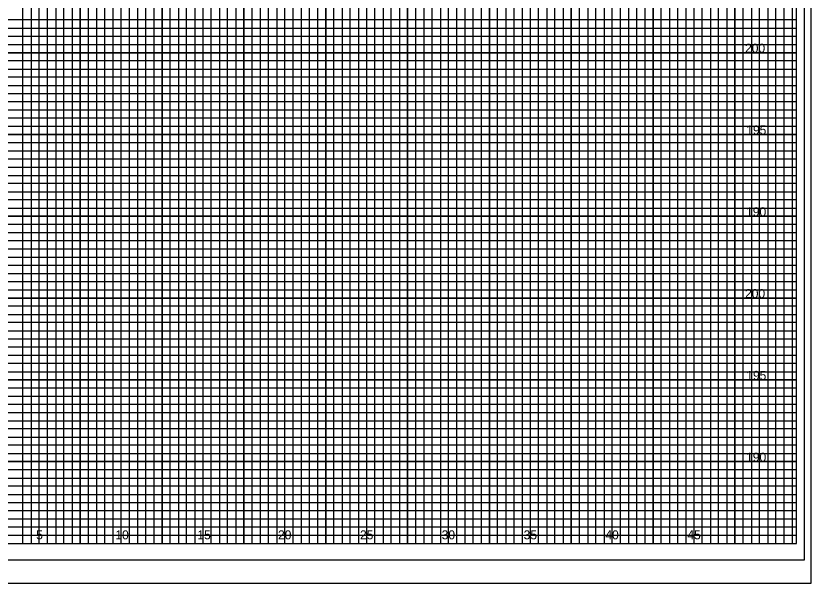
# Model space of a CAD drawing. Extents: x -4 to 103, y -2 to 209.
# Drawn here: x 54.82 to 103.4, y -2.43 to 32.25 of the extents above; entities that cross this region are included whole.
import ezdxf

# ---------------------------------------------------------------- set-up
doc = ezdxf.new("R2010")
doc.units = 0
for name, color, linetype in [('Exist XS Ground Line', 7, 'Continuous'), ('Old_Level_10', 7, 'Continuous'), ('Old_Level_3', 7, 'Continuous'), ('Old_Level_5', 7, 'Continuous'), ('Old_Level_8', 7, 'Continuous'), ('Prop XS Dump Level', 7, 'Continuous'), ('Prop XS Elevation Labels', 7, 'Continuous'), ('Prop XS Finish Grade', 7, 'Continuous'), ('Prop XS Label Text', 7, 'Continuous')]:
    doc.layers.add(name, color=color, linetype=linetype)

msp = doc.modelspace()

# ---------------------------------------------------------------- linework, layer by layer
at = {"layer": 'Exist XS Ground Line'}
msp.add_lwpolyline([(103, 66), (-2.8, 66), (-2.8, -1), (103, -1)], close=True, dxfattribs=at)
at = {"layer": 'Old_Level_10'}
for p, q in [((56.25, 0), (56.25, 65)), ((58.75, 0), (58.75, 65)), ((61.25, 0), (61.25, 65)), ((63.75, 0), (63.75, 65)), ((66.25, 0), (66.25, 65)), ((68.75, 0), (68.75, 65)), ((71.25, 0), (71.25, 65)), ((73.75, 0), (73.75, 65)), ((91.25, 0), (91.25, 63.425)), ((93.75, 0), (93.75, 63.425)), ((96.25, 0), (96.25, 63.425)), ((98.75, 0), (98.75, 63.425)), ((101.25, 0), (101.25, 63.425)), ((76.25, 0), (76.25, 62)), ((78.75, 0), (78.75, 62)), ((81.25, 0), (81.25, 62)), ((83.75, 0), (83.75, 62)), ((86.25, 0), (86.25, 62)), ((88.75, 0), (88.75, 62)), ((0, 30), (102.5, 30)), ((0, 27.5), (102.5, 27.5)), ((0, 25), (102.5, 25)), ((0, 22.5), (102.5, 22.5)), ((0, 20), (102.5, 20)), ((0, 17.5), (102.5, 17.5)), ((0, 15), (102.5, 15)), ((0, 12.5), (102.5, 12.5)), ((0, 10), (102.5, 10)), ((0, 7.5), (102.5, 7.5)), ((0, 5), (102.5, 5)), ((0, 2.5), (102.5, 2.5))]:
    msp.add_line(p, q, dxfattribs=at)
at = {"layer": 'Old_Level_3'}
msp.add_line((-3.5, -2.425), (103.4, -2.425), dxfattribs=at)
at = {"layer": 'Old_Level_5'}
msp.add_lwpolyline([(103.4, 67.4), (-3.5, 67.4), (-3.5, -2.425), (103.4, -2.425)], close=True, dxfattribs=at)
at = {"layer": 'Old_Level_8'}
for points in [[(56.25, 0), (56.25, 65)], [(58.75, 65), (58.75, 0), (61.25, 0), (61.25, 65)], [(63.75, 65), (63.75, 0), (66.25, 0), (66.25, 65)], [(68.75, 65), (68.75, 0), (71.25, 0), (71.25, 65)], [(73.75, 65), (73.75, 0), (76.25, 0), (76.25, 62)], [(88.75, 62), (88.75, 0), (91.25, 0), (91.25, 63.425)], [(93.75, 63.425), (93.75, 0), (96.25, 0), (96.25, 63.425)], [(98.75, 63.425), (98.75, 0), (101.25, 0), (101.25, 63.425)], [(78.75, 62), (78.75, 0), (81.25, 0), (81.25, 62)], [(83.75, 62), (83.75, 0), (86.25, 0), (86.25, 62)], [(0, 27.5), (102.5, 27.5), (102.5, 30), (0, 30)], [(0, 22.5), (102.5, 22.5), (102.5, 25), (0, 25)], [(0, 17.5), (102.5, 17.5), (102.5, 20), (0, 20)], [(0, 12.5), (102.5, 12.5), (102.5, 15), (0, 15)], [(0, 7.5), (102.5, 7.5), (102.5, 10), (0, 10)], [(0, 2.5), (102.5, 2.5), (102.5, 5), (0, 5)]]:
    msp.add_lwpolyline(points, dxfattribs=at)
at = {"layer": 'Prop XS Dump Level'}
msp.add_lwpolyline([(102.5, 65), (0, 65), (0, 0), (102.5, 0)], close=True, dxfattribs=at)
at = {"layer": 'Prop XS Finish Grade'}
for points in [[(54.75, 0), (55.25, 0), (55.25, 65)], [(55.75, 65), (55.75, 0), (56.75, 0), (56.75, 65)], [(57.25, 65), (57.25, 0), (57.75, 0), (57.75, 65)], [(58.25, 65), (58.25, 0), (59.25, 0), (59.25, 65)], [(59.75, 65), (59.75, 0), (60.25, 0), (60.25, 65)], [(60.75, 65), (60.75, 0), (61.75, 0), (61.75, 65)], [(62.25, 65), (62.25, 0), (62.75, 0), (62.75, 65)], [(63.25, 65), (63.25, 0), (64.25, 0), (64.25, 65)], [(64.75, 65), (64.75, 0), (65.25, 0), (65.25, 65)], [(65.75, 65), (65.75, 0), (66.75, 0), (66.75, 65)], [(67.25, 65), (67.25, 0), (67.75, 0), (67.75, 65)], [(68.25, 65), (68.25, 0), (69.25, 0), (69.25, 65)], [(69.75, 65), (69.75, 0), (70.25, 0), (70.25, 65)], [(70.75, 65), (70.75, 0), (71.75, 0), (71.75, 65)], [(72.25, 65), (72.25, 0), (72.75, 0), (72.75, 65)], [(73.25, 65), (73.25, 0), (74.25, 0), (74.25, 62)], [(89.75, 62), (89.75, 0), (90.25, 0), (90.25, 63.425)], [(90.75, 63.425), (90.75, 0), (91.75, 0), (91.75, 63.425)], [(92.25, 63.425), (92.25, 0), (92.75, 0), (92.75, 63.425)], [(93.25, 63.425), (93.25, 0), (94.25, 0), (94.25, 63.425)], [(94.75, 63.425), (94.75, 0), (95.25, 0), (95.25, 63.425)], [(95.75, 63.425), (95.75, 0), (96.75, 0), (96.75, 63.425)], [(97.25, 63.425), (97.25, 0), (97.75, 0), (97.75, 63.425)], [(98.25, 63.425), (98.25, 0), (99.25, 0), (99.25, 63.425)], [(99.75, 63.425), (99.75, 0), (100.25, 0), (100.25, 63.425)], [(100.25, 63.425), (100.75, 63.425), (100.75, 0), (101.75, 0), (101.75, 63.425), (102.25, 63.425), (102.25, 0)], [(74.75, 62), (74.75, 0), (75.25, 0), (75.25, 62)], [(75.75, 62), (75.75, 0), (76.75, 0), (76.75, 62)], [(77.25, 62), (77.25, 0), (77.75, 0), (77.75, 62)], [(78.25, 62), (78.25, 0), (79.25, 0), (79.25, 62)], [(79.75, 62), (79.75, 0), (80.25, 0), (80.25, 62)], [(80.75, 62), (80.75, 0), (81.75, 0), (81.75, 62)], [(82.25, 62), (82.25, 0), (82.75, 0), (82.75, 62)], [(83.25, 62), (83.25, 0), (84.25, 0), (84.25, 62)], [(84.75, 62), (84.75, 0), (85.25, 0), (85.25, 62)], [(85.75, 62), (85.75, 0), (86.75, 0), (86.75, 62)], [(87.25, 62), (87.25, 0), (87.75, 0), (87.75, 62)], [(88.25, 62), (88.25, 0), (89.25, 0), (89.25, 62)], [(0, 31.5), (102.5, 31.5), (102.5, 32), (0, 32)], [(0, 30.5), (102.5, 30.5), (102.5, 31), (0, 31)], [(0, 29), (102.5, 29), (102.5, 29.5), (0, 29.5)], [(0, 28), (102.5, 28), (102.5, 28.5), (0, 28.5)], [(0, 26.5), (102.5, 26.5), (102.5, 27), (0, 27)], [(0, 25.5), (102.5, 25.5), (102.5, 26), (0, 26)], [(0, 24), (102.5, 24), (102.5, 24.5), (0, 24.5)], [(0, 23), (102.5, 23), (102.5, 23.5), (0, 23.5)], [(0, 21.5), (102.5, 21.5), (102.5, 22), (0, 22)], [(0, 20.5), (102.5, 20.5), (102.5, 21), (0, 21)], [(0, 19), (102.5, 19), (102.5, 19.5), (0, 19.5)], [(0, 18), (102.5, 18), (102.5, 18.5), (0, 18.5)], [(0, 16.5), (102.5, 16.5), (102.5, 17), (0, 17)], [(0, 15.5), (102.5, 15.5), (102.5, 16), (0, 16)], [(0, 14), (102.5, 14), (102.5, 14.5), (0, 14.5)], [(0, 13), (102.5, 13), (102.5, 13.5), (0, 13.5)], [(0, 11.5), (102.5, 11.5), (102.5, 12), (0, 12)], [(0, 10.5), (102.5, 10.5), (102.5, 11), (0, 11)], [(0, 9), (102.5, 9), (102.5, 9.5), (0, 9.5)], [(0, 8), (102.5, 8), (102.5, 8.5), (0, 8.5)], [(0, 6.5), (102.5, 6.5), (102.5, 7), (0, 7)], [(0, 5.5), (102.5, 5.5), (102.5, 6), (0, 6)], [(0, 4), (102.5, 4), (102.5, 4.5), (0, 4.5)], [(0, 3), (102.5, 3), (102.5, 3.5), (0, 3.5)], [(0, 1.5), (102.5, 1.5), (102.5, 2), (0, 2)], [(0, 0.5), (102.5, 0.5), (102.5, 1), (0, 1)]]:
    msp.add_lwpolyline(points, dxfattribs=at)

# ---------------------------------------------------------------- texts
at = {"layer": 'Prop XS Elevation Labels'}
for s, p in [('5', (56.0574, 0.25)), ('10', (60.8971, 0.25)), ('15', (65.9057, 0.25)), ('20', (70.8312, 0.25)), ('25', (75.8399, 0.25)), ('30', (80.8312, 0.25)), ('35', (85.8399, 0.25)), ('40', (90.8313, 0.25)), ('45', (95.8399, 0.25))]:
    msp.add_text(s, height=0.55, dxfattribs=at).set_placement(p)
at = {"layer": 'Prop XS Label Text'}
for s, p in [('200', (99.3638, 30)), ('195', (99.4383, 25)), ('190', (99.4296, 20)), ('200', (99.3638, 15)), ('195', (99.4383, 10)), ('190', (99.4296, 5))]:
    msp.add_text(s, height=0.55, dxfattribs=at).set_placement(p)

doc.saveas('drawing.dxf')
